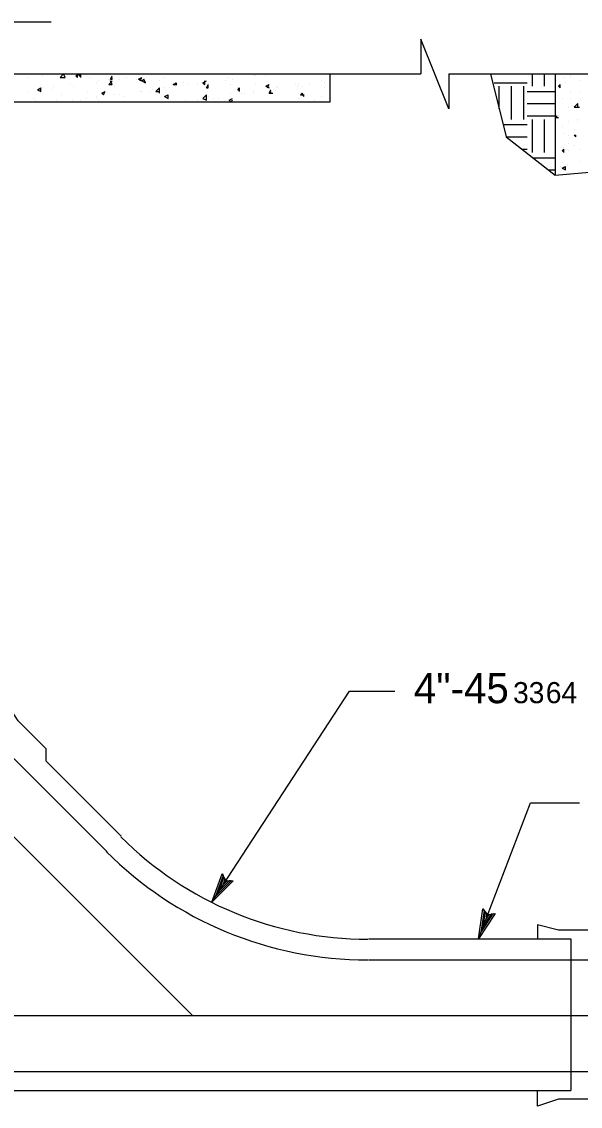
# Model space of a CAD drawing. Extents: x -119017 to -116080, y -104449 to -102845.
# Drawn here: x -116398.8 to -116287.5, y -103493.5 to -103277.6 of the extents above; entities that cross this region are included whole.
import ezdxf

# ---------------------------------------------------------------- set-up
doc = ezdxf.new("R2010")
doc.units = 0
for name, color, linetype in [('G-MARK', 7, 'Continuous'), ('G-TEXT', 7, 'Continuous'), ('Misc CnstDet(22)', 7, 'Continuous')]:
    doc.layers.add(name, color=color, linetype=linetype)

msp = doc.modelspace()

# ---------------------------------------------------------------- linework, layer by layer
at = {"layer": 'G-MARK'}
msp.add_line((-116431.07, -103277.64), (-116392.89, -103277.64), dxfattribs=at)
for points in [[(-116360.95, -103452.92), (-116333.53, -103410.92), (-116324.51, -103410.92)], [(-116307.85, -103460.21), (-116297.43, -103433.14), (-116287.72, -103433.14)]]:
    msp.add_lwpolyline(points, dxfattribs=at)
at = {"layer": 'G-TEXT'}
for points in [[(-116356.65, -103448.67), (-116360.95, -103452.92), (-116358.86, -103447.25), (-116358.68, -103447.61), (-116360.21, -103451.77), (-116357.05, -103448.66), (-116357.46, -103448.64), (-116359.48, -103450.64), (-116358.5, -103447.98), (-116358.32, -103448.34), (-116358.74, -103449.49), (-116357.87, -103448.63), (-116358.18, -103448.62), (-116358.86, -103447.25), (-116358.18, -103448.62)], [(-116304.5, -103455.17), (-116307.85, -103460.21), (-116306.95, -103454.23), (-116306.7, -103454.55), (-116307.36, -103458.93), (-116304.9, -103455.24), (-116305.3, -103455.31), (-116306.87, -103457.67), (-116306.45, -103454.87), (-116306.2, -103455.19), (-116306.38, -103456.4), (-116305.7, -103455.38), (-116306.01, -103455.43), (-116306.95, -103454.23), (-116306.01, -103455.43)]]:
    msp.add_lwpolyline(points, close=True, dxfattribs=at)
at = {"layer": 'Misc CnstDet(22)'}
for p, q in [((-116319.3, -103281.11), (-116319.3, -103288.05)), ((-116313.75, -103294.99), (-116319.3, -103281.11)), ((-116614.33, -103288.05), (-116319.3, -103288.05)), ((-116398.09, -103288.05), (-116398.09, -103288.05)), ((-116394.62, -103288.4), (-116394.62, -103288.4)), ((-116392.89, -103288.05), (-116392.89, -103288.05)), ((-116391.15, -103288.75), (-116390.46, -103288.05)), ((-116390.11, -103288.75), (-116390.46, -103288.05)), ((-116388.03, -103288.4), (-116387.33, -103288.05)), ((-116388.03, -103288.4), (-116387.68, -103288.75)), ((-116387.68, -103288.75), (-116387.68, -103288.05)), ((-116387.33, -103288.4), (-116386.98, -103288.05)), ((-116387.33, -103288.4), (-116386.98, -103288.4)), ((-116386.98, -103288.75), (-116386.98, -103288.05)), ((-116381.08, -103289.09), (-116380.74, -103288.4)), ((-116352.62, -103288.4), (-116352.62, -103288.4)), ((-116352.28, -103288.4), (-116352.28, -103288.4)), ((-116350.19, -103288.4), (-116350.19, -103288.4)), ((-116337.35, -103293.61), (-116337.35, -103288.05)), ((-116313.75, -103288.05), (-116284.94, -103288.05)), ((-116313.75, -103288.05), (-116313.75, -103294.99)), ((-116297.09, -103290.48), (-116297.09, -103288.05)), ((-116294.66, -103290.48), (-116294.66, -103288.05)), ((-116292.58, -103288.05), (-116292.58, -103308.18)), ((-116289.45, -103288.4), (-116289.45, -103288.4)), ((-116397.4, -103288.75), (-116397.4, -103288.75)), ((-116392.54, -103290.48), (-116392.54, -103290.48)), ((-116391.15, -103288.75), (-116390.11, -103288.75)), ((-116390.11, -103288.75), (-116390.11, -103288.75)), ((-116389.07, -103290.13), (-116389.07, -103290.13)), ((-116388.37, -103290.48), (-116388.37, -103290.48)), ((-116385.25, -103288.75), (-116385.25, -103288.75)), ((-116383.86, -103289.79), (-116383.86, -103289.79)), ((-116383.51, -103289.44), (-116383.51, -103289.44)), ((-116381.43, -103289.09), (-116381.43, -103289.09)), ((-116381.43, -103290.13), (-116380.74, -103289.44)), ((-116381.43, -103290.13), (-116380.74, -103290.13)), ((-116381.08, -103289.09), (-116380.74, -103289.09)), ((-116380.74, -103290.13), (-116381.08, -103289.44)), ((-116380.74, -103289.09), (-116380.74, -103288.75)), ((-116380.74, -103289.09), (-116380.74, -103289.09)), ((-116380.39, -103290.48), (-116380.39, -103290.48)), ((-116379.35, -103289.09), (-116379.35, -103289.09)), ((-116377.96, -103288.75), (-116377.96, -103288.75)), ((-116375.88, -103289.09), (-116375.88, -103289.09)), ((-116375.53, -103289.09), (-116374.84, -103288.75)), ((-116375.53, -103289.09), (-116374.84, -103289.44)), ((-116375.18, -103289.44), (-116374.84, -103288.75)), ((-116375.18, -103289.44), (-116375.18, -103289.44)), ((-116374.84, -103288.75), (-116374.84, -103288.75)), ((-116374.84, -103289.44), (-116374.49, -103289.09)), ((-116374.84, -103289.44), (-116374.14, -103289.79)), ((-116374.14, -103289.79), (-116374.49, -103289.09)), ((-116371.37, -103289.44), (-116371.37, -103289.44)), ((-116370.32, -103288.75), (-116370.32, -103288.75)), ((-116368.59, -103290.13), (-116367.89, -103289.79)), ((-116368.59, -103290.13), (-116367.89, -103290.13)), ((-116367.89, -103290.13), (-116368.24, -103289.79)), ((-116368.24, -103290.48), (-116368.24, -103290.48)), ((-116366.51, -103289.79), (-116366.51, -103289.79)), ((-116365.81, -103290.13), (-116365.81, -103290.13)), ((-116363.73, -103290.13), (-116363.73, -103290.13)), ((-116363.04, -103289.79), (-116363.04, -103289.79)), ((-116362.69, -103289.79), (-116361.99, -103289.44)), ((-116362.69, -103289.79), (-116362.34, -103290.13)), ((-116362.34, -103290.13), (-116362.34, -103289.44)), ((-116361.99, -103290.83), (-116361.65, -103290.13)), ((-116361.65, -103289.79), (-116361.65, -103289.79)), ((-116361.65, -103289.79), (-116361.65, -103289.79)), ((-116361.65, -103289.79), (-116361.65, -103289.79)), ((-116361.65, -103290.83), (-116361.65, -103290.13)), ((-116358.18, -103289.44), (-116358.18, -103289.44)), ((-116357.83, -103288.75), (-116357.83, -103288.75)), ((-116357.13, -103290.13), (-116357.13, -103290.13)), ((-116356.79, -103289.09), (-116356.79, -103289.09)), ((-116352.28, -103290.13), (-116352.28, -103290.13)), ((-116350.19, -103290.48), (-116349.5, -103290.13)), ((-116350.19, -103290.48), (-116349.5, -103290.83)), ((-116349.85, -103290.83), (-116349.5, -103290.13)), ((-116347.76, -103290.48), (-116347.76, -103290.48)), ((-116344.29, -103290.13), (-116344.29, -103290.13)), ((-116343.95, -103290.48), (-116343.95, -103290.48)), ((-116343.6, -103290.13), (-116343.6, -103290.13)), ((-116342.9, -103290.48), (-116342.9, -103290.48)), ((-116341.52, -103290.13), (-116341.52, -103290.13)), ((-116339.09, -103289.44), (-116339.09, -103289.44)), ((-116339.09, -103289.44), (-116339.09, -103289.44)), ((-116338.39, -103289.79), (-116338.39, -103289.79)), ((-116304.72, -103289.79), (-116298.13, -103289.79)), ((-116303.68, -103294.99), (-116303.68, -103290.48)), ((-116301.25, -103297.08), (-116301.25, -103290.48)), ((-116298.82, -103297.08), (-116298.82, -103290.48)), ((-116292.23, -103289.44), (-116292.23, -103289.44)), ((-116291.88, -103290.48), (-116291.53, -103290.13)), ((-116291.88, -103290.48), (-116291.53, -103290.83)), ((-116291.53, -103290.83), (-116291.53, -103290.13)), ((-116290.84, -103288.75), (-116290.84, -103288.75)), ((-116290.49, -103289.79), (-116290.49, -103289.79)), ((-116289.45, -103288.75), (-116289.45, -103288.75)), ((-116287.72, -103289.44), (-116287.72, -103289.44)), ((-116397.4, -103291.52), (-116397.4, -103291.52)), ((-116396.36, -103292.91), (-116396.36, -103292.91)), ((-116395.66, -103291.18), (-116394.97, -103290.83)), ((-116395.66, -103291.18), (-116394.97, -103291.52)), ((-116394.97, -103291.52), (-116394.97, -103290.83)), ((-116394.62, -103290.83), (-116394.62, -103290.83)), ((-116392.89, -103291.18), (-116392.89, -103291.18)), ((-116390.8, -103292.22), (-116390.8, -103292.22)), ((-116385.94, -103292.91), (-116385.94, -103292.91)), ((-116385.6, -103291.52), (-116385.6, -103291.52)), ((-116383.86, -103292.56), (-116383.86, -103292.56)), ((-116383.86, -103292.91), (-116383.86, -103292.91)), ((-116382.82, -103291.87), (-116382.13, -103291.52)), ((-116382.82, -103291.87), (-116382.47, -103292.22)), ((-116382.47, -103292.22), (-116382.13, -103291.52)), ((-116380.39, -103292.22), (-116380.39, -103292.22)), ((-116379.35, -103292.22), (-116379.35, -103292.22)), ((-116378.31, -103292.56), (-116378.31, -103292.56)), ((-116375.18, -103291.52), (-116375.18, -103291.52)), ((-116374.84, -103291.52), (-116374.84, -103291.52)), ((-116373.1, -103291.52), (-116373.1, -103291.52)), ((-116372.75, -103291.18), (-116372.75, -103291.18)), ((-116372.06, -103291.52), (-116371.37, -103290.83)), ((-116372.06, -103291.52), (-116371.37, -103291.52)), ((-116371.37, -103291.87), (-116371.37, -103290.83)), ((-116370.32, -103290.83), (-116370.32, -103290.83)), ((-116370.32, -103292.56), (-116369.63, -103292.22)), ((-116370.32, -103292.56), (-116369.63, -103292.91)), ((-116369.63, -103292.91), (-116369.63, -103292.22)), ((-116369.28, -103290.83), (-116369.28, -103290.83)), ((-116362.69, -103292.91), (-116361.99, -103292.22)), ((-116362.69, -103292.91), (-116361.99, -103293.26)), ((-116361.99, -103290.83), (-116361.65, -103290.83)), ((-116361.99, -103293.26), (-116361.99, -103292.22)), ((-116361.65, -103292.56), (-116361.65, -103292.56)), ((-116360.61, -103292.91), (-116360.61, -103292.91)), ((-116359.56, -103292.91), (-116359.56, -103292.91)), ((-116357.48, -103293.26), (-116356.79, -103292.91)), ((-116357.13, -103291.87), (-116357.13, -103291.87)), ((-116355.75, -103291.18), (-116355.4, -103290.83)), ((-116355.75, -103291.18), (-116355.4, -103291.18)), ((-116355.4, -103291.52), (-116355.4, -103290.83)), ((-116355.05, -103291.87), (-116355.05, -103291.87)), ((-116354.36, -103291.87), (-116354.36, -103291.87)), ((-116352.62, -103291.52), (-116352.62, -103291.52)), ((-116352.62, -103291.87), (-116352.62, -103291.87)), ((-116349.5, -103291.18), (-116349.5, -103291.18)), ((-116349.5, -103291.87), (-116349.15, -103291.18)), ((-116349.5, -103291.87), (-116348.8, -103291.87)), ((-116349.15, -103291.18), (-116349.15, -103291.18)), ((-116349.15, -103291.87), (-116349.15, -103291.52)), ((-116348.11, -103290.83), (-116348.11, -103290.83)), ((-116343.6, -103292.91), (-116343.6, -103292.91)), ((-116343.25, -103292.22), (-116342.9, -103291.87)), ((-116343.25, -103292.22), (-116342.56, -103292.22)), ((-116342.56, -103292.56), (-116342.9, -103291.87)), ((-116339.09, -103292.56), (-116339.09, -103292.56)), ((-116338.39, -103290.83), (-116338.39, -103290.83)), ((-116337.35, -103291.18), (-116337.35, -103291.18)), ((-116337.35, -103291.18), (-116337.35, -103291.18)), ((-116298.13, -103291.52), (-116292.58, -103291.52)), ((-116291.19, -103292.91), (-116291.19, -103292.91)), ((-116289.45, -103291.52), (-116289.45, -103291.52)), ((-116289.45, -103292.91), (-116289.45, -103292.91)), ((-116287.72, -103291.52), (-116287.72, -103291.52)), ((-116431.07, -103293.61), (-116337.35, -103293.61)), ((-116398.44, -103293.61), (-116398.44, -103293.61)), ((-116398.44, -103293.61), (-116398.44, -103293.61)), ((-116396.01, -103293.26), (-116396.01, -103293.26)), ((-116391.84, -103293.26), (-116391.84, -103293.26)), ((-116388.72, -103293.26), (-116388.72, -103293.26)), ((-116386.98, -103293.26), (-116386.98, -103293.26)), ((-116383.51, -103293.26), (-116383.51, -103293.26)), ((-116382.47, -103293.61), (-116382.47, -103293.61)), ((-116366.16, -103293.26), (-116366.16, -103293.26)), ((-116366.16, -103293.61), (-116366.16, -103293.61)), ((-116363.73, -103293.26), (-116363.73, -103293.26)), ((-116357.48, -103293.26), (-116357.13, -103293.61)), ((-116357.13, -103293.61), (-116356.79, -103293.26)), ((-116340.47, -103293.26), (-116340.47, -103293.26)), ((-116298.13, -103293.95), (-116292.58, -103293.95)), ((-116289.8, -103294.65), (-116289.8, -103294.65)), ((-116288.76, -103294.65), (-116288.06, -103293.95)), ((-116288.76, -103294.65), (-116287.72, -103294.65)), ((-116288.06, -103294.65), (-116288.06, -103293.95)), ((-116298.13, -103296.38), (-116292.58, -103296.38)), ((-116297.09, -103303.67), (-116297.09, -103297.08)), ((-116294.66, -103303.67), (-116294.66, -103297.08)), ((-116292.58, -103296.73), (-116292.23, -103296.38)), ((-116292.58, -103296.73), (-116291.88, -103296.73)), ((-116292.23, -103296.73), (-116292.23, -103296.38)), ((-116291.88, -103296.38), (-116291.88, -103296.38)), ((-116288.06, -103297.08), (-116288.06, -103297.08)), ((-116302.99, -103298.12), (-116298.13, -103298.12)), ((-116291.19, -103298.46), (-116291.19, -103298.46)), ((-116289.8, -103297.42), (-116289.8, -103297.42)), ((-116288.76, -103299.16), (-116288.76, -103299.16)), ((-116288.06, -103297.42), (-116288.06, -103297.42)), ((-116302.29, -103300.55), (-116298.13, -103300.55)), ((-116290.84, -103299.85), (-116290.84, -103299.85)), ((-116289.8, -103300.2), (-116289.8, -103300.2)), ((-116288.76, -103300.2), (-116288.41, -103300.55)), ((-116288.76, -103300.2), (-116288.41, -103300.2)), ((-116288.41, -103300.55), (-116288.41, -103300.2)), ((-116299.17, -103302.98), (-116298.13, -103302.98)), ((-116291.19, -103303.32), (-116290.84, -103302.98)), ((-116291.19, -103303.32), (-116290.84, -103303.32)), ((-116290.84, -103302.63), (-116290.84, -103302.63)), ((-116290.84, -103303.67), (-116290.84, -103302.98)), ((-116289.8, -103301.94), (-116289.8, -103301.94)), ((-116289.8, -103303.32), (-116289.8, -103303.32)), ((-116288.76, -103302.28), (-116288.76, -103302.28)), ((-116287.72, -103302.98), (-116287.72, -103302.98)), ((-116297.09, -103304.71), (-116292.58, -103304.71)), ((-116291.19, -103305.75), (-116291.19, -103305.75)), ((-116287.72, -103305.41), (-116287.72, -103305.41)), ((-116293.96, -103307.14), (-116292.58, -103307.14)), ((-116292.58, -103308.18), (-116272.1, -103306.45)), ((-116291.53, -103306.45), (-116291.53, -103306.45)), ((-116291.19, -103306.79), (-116290.49, -103306.45)), ((-116291.19, -103306.79), (-116290.49, -103307.14)), ((-116290.49, -103307.14), (-116290.49, -103306.45)), ((-116290.15, -103306.1), (-116290.15, -103306.1)), ((-116289.8, -103307.84), (-116289.8, -103307.84)), ((-116364.77, -103475.48), (-116518.53, -103321.72)), ((-116381.78, -103442.85), (-116487.29, -103337.69)), ((-116379, -103439.73), (-116393.93, -103424.81)), ((-116329.71, -103460.21), (-116289.45, -103460.21)), ((-116289.45, -103460.21), (-116289.45, -103490.41)), ((-116329.71, -103464.37), (-116251.62, -103464.37)), ((-116462.65, -103475.48), (-116242.25, -103475.48)), ((-116421.69, -103486.59), (-116246.76, -103486.59)), ((-116421.69, -103490.41), (-116289.45, -103490.41))]:
    msp.add_line(p, q, dxfattribs=at)
for points in [[(-116305.42, -103288.05), (-116302.29, -103300.55), (-116292.58, -103308.18)], [(-116393.93, -103424.81), (-116393.93, -103422.38), (-116399.48, -103416.82), (-116401.91, -103413), (-116403.64, -103415.09)], [(-116282.16, -103460.21), (-116283.9, -103458.47), (-116291.88, -103458.47), (-116296.05, -103457.43), (-116296.05, -103460.21)], [(-116282.16, -103490.41), (-116283.9, -103492.14), (-116291.88, -103492.14), (-116296.05, -103493.53), (-116296.05, -103490.41)]]:
    msp.add_lwpolyline(points, dxfattribs=at)
for radius in [69.49, 73.62]:
    msp.add_arc((-116329.88, -103390.77), radius, 225, 270, dxfattribs=at)

# ---------------------------------------------------------------- texts
for s, height, p in [('4"-45', 6, (-116320.69, -103413.29)), ('33', 4.2, (-116300.94, -103413.29)), ('64', 4.2, (-116294.42, -103413.29))]:
    msp.add_text(s, height=height, dxfattribs=at).set_placement(p)

doc.saveas('drawing.dxf')
